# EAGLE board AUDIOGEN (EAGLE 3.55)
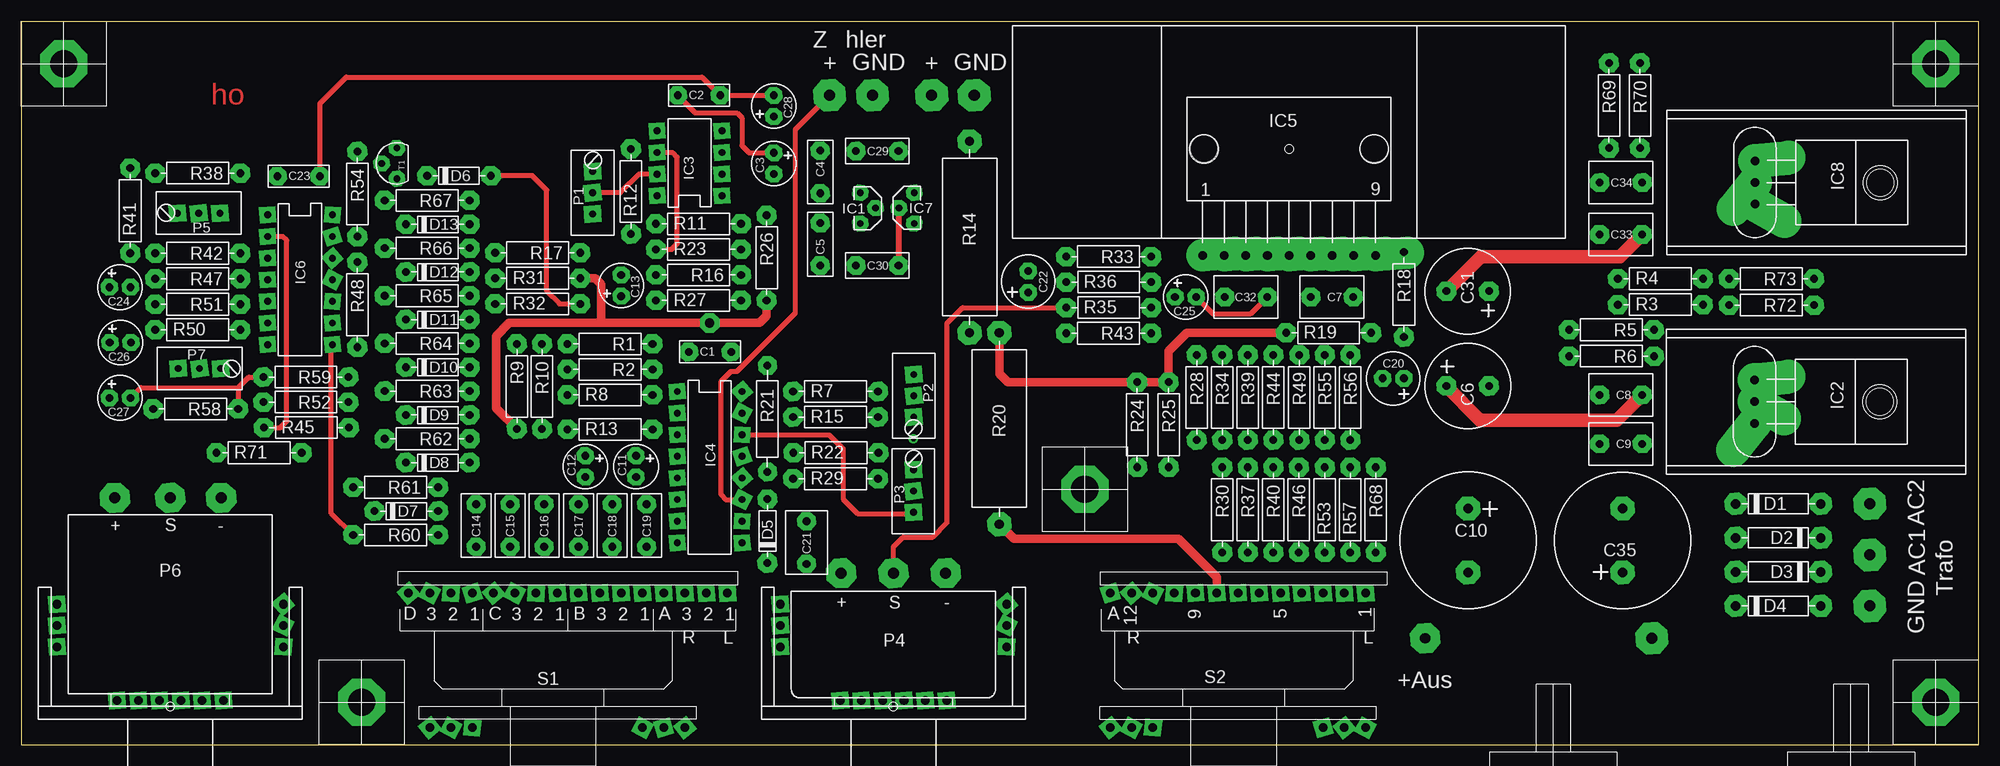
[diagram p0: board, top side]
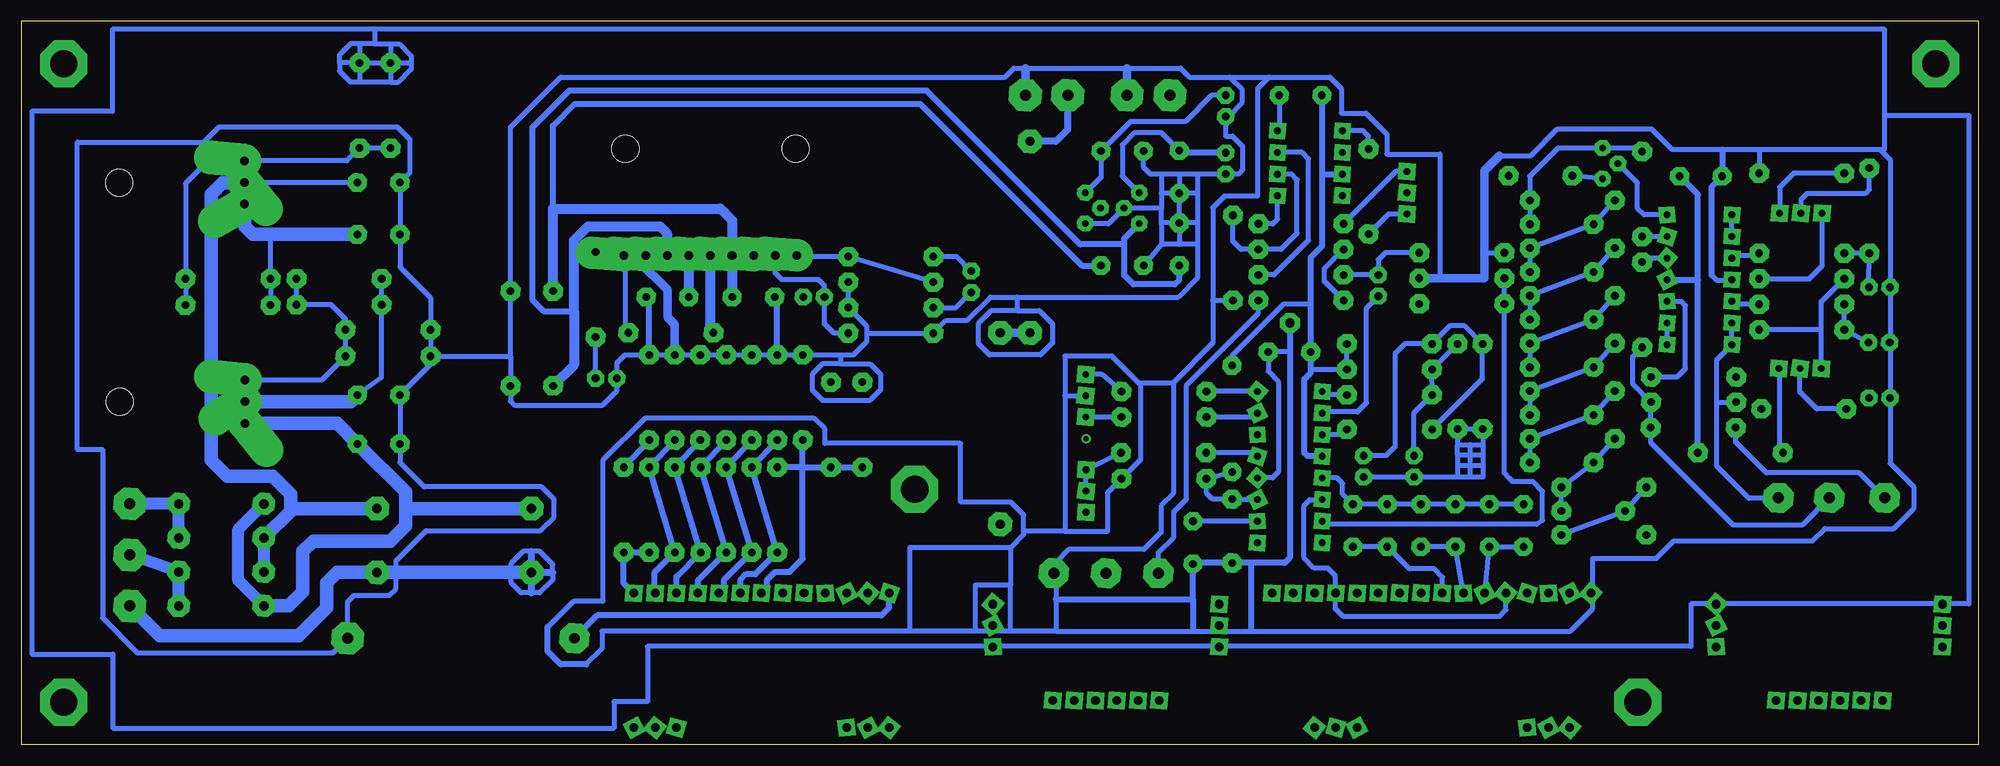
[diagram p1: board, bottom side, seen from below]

Size 230 x 85 mm. Coordinates in mm from the lower left corner, seen from the top.
Outline: 0,85 0,0 230,0 230,85 0,85
Copper layers used: Top, Bottom

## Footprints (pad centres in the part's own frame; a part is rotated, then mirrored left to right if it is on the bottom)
AD-3,8 = drill 1.3 pad 3.8 octagon:  0,0
5-2,8 = drill 0.9 pad 2.2 octagon:  0,0;  5,0
5-R2,5 = drill 0.9 pad 2 octagon:  0,0;  0,2.5
5-3,0 = drill 0.9 pad 2.2 octagon:  0,0;  5,0
0-R5 = drill 0.9 pad 2.3 octagon:  0,0;  0,5
-5,0 = drill 0.9 pad 2.2 octagon:  0,0;  5,0
6-R7,5 = drill 1.1 pad 2.8 octagon:  0,0;  0,7.5
5-3,5 = drill 0.9 pad 2.2 octagon:  0,0;  5,0
6-R2,5 = drill 0.9 pad 2 octagon:  0,0;  0,2.5
5-5,0 = drill 0.9 pad 2.2 octagon:  0,0;  5,0
10-2 = drill 1.1 pad 2.6 octagon:  0,0;  10,0
7,5 = drill 0.9 pad 2.3 octagon:  0,0;  7.5,0
L00 = drill 0.8 pad 1.9 octagon:  -1.8,1.8;  0,3.6;  0,0
317-LK = drill 1 pad 4 offset:  0,-14.75;  2.54,-14.75;  -2.54,-14.75 | hole 3.2: 0,0
L08 = drill 0.8 pad 1.9 square:  0,0;  2.54,0;  5.08,0;  7.62,0;  7.62,7.62;  5.08,7.62;  2.54,7.62;  0,7.62
L16 = drill 0.8 pad 1.9 square:  0,0;  2.54,0;  5.08,0;  7.62,0;  10.16,0;  12.7,0;  15.24,0;  17.78,0;  17.78,7.62;  15.24,7.62;  12.7,7.62;  10.16,7.62;  7.62,7.62;  5.08,7.62;  2.54,7.62;  0,7.62
A1514 = drill 1 pad 3.8 offset:  0,-12.5;  -10.16,-12.5;  -7.62,-12.5;  -5.08,-12.5;  -2.54,-12.5;  2.54,-12.5;  5.08,-12.5;  7.62,-12.5;  10.16,-12.5 | hole 3.2: -10,0; 10,0
L14 = drill 0.8 pad 1.9 square:  0,0;  2.54,0;  5.08,0;  7.62,0;  10.16,0;  12.7,0;  15.24,0;  15.24,7.62;  12.7,7.62;  10.16,7.62;  7.62,7.62;  5.08,7.62;  2.54,7.62;  0,7.62
337-LK = drill 1 pad 4 offset:  0,-14.75;  2.54,-14.75;  -2.54,-14.75 | hole 3.2: 0,0
AD-3,5 = drill 1.2 pad 3.5 octagon:  0,0
IMM-S1 = drill 0.8 pad 2 square:  0,0;  2.5,0;  -2.5,0
NTUR-1 = drill 1 pad 2 square:  -13.3,7;  -13.3,9.5;  -13.3,12;  13.3,12;  13.3,9.5;  13.3,7;  6.25,0.7;  3.75,0.7;  1.25,0.7;  -1.25,0.7;  -3.75,0.7;  -6.25,0.7 | drill 1.3 pad 3.5 octagon:  0,15.65;  6.15,15.65;  -6.15,15.65
NTUR-2 = drill 1 pad 2 square:  -13.3,7;  -13.3,9.5;  -13.3,12;  13.3,12;  13.3,9.5;  13.3,7;  6.25,0.7;  3.75,0.7;  1.25,0.7;  -1.25,0.7;  -3.75,0.7;  -6.25,0.7 | drill 1.3 pad 3.5 octagon:  0,24.5;  -6.5,24.5;  6,24.5
10 = drill 0.9 pad 2.3 octagon:  0,0;  10,0
D-6X18 = drill 1.1 pad 2.8 octagon:  0,0;  22.5,0
12,5 = drill 0.9 pad 2.2 octagon:  0,0;  12.5,0
4X03 = drill 1 pad 2 square:  -14.5,13.3;  -12,13.3;  -9.5,13.3;  -7,13.3;  -4.5,13.3;  -2,13.3;  0.5,13.3;  3,13.3;  5.5,13.3;  8,13.3;  10.5,13.3;  13,13.3;  15.5,13.3;  18,13.3;  -14.5,-2.5;  -12,-2.5;  -9.5,-2.5;  13,-2.5;  15.5,-2.5;  10.5,-2.5;  20.5,13.3;  -17,13.3
1X12 = drill 1 pad 2 square:  -14.5,13.3;  -12,13.3;  -9.5,13.3;  -7,13.3;  -4.5,13.3;  -2,13.3;  0.5,13.3;  3,13.3;  5.5,13.3;  8,13.3;  10.5,13.3;  13,13.3;  15.5,13.3;  -14.5,-2.5;  -12,-2.5;  -9.5,-2.5;  13,-2.5;  15.5,-2.5;  10.5,-2.5
-TO92 = drill 0.8 pad 1.9 octagon:  1.8,1.8;  3.6,0;  0,0

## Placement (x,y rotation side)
-VAC  GND  [AD-3,8]  217.25,16.3 0 top
BEF1  [F10]  5,80 0 top
BEF2  [F10]  225,80 0 top
BEF3  [F10]  40,5 0 top
BEF4  [F10]  125,30 0 top
BEF5  [F10]  225,5 0 top
C1  100n  [5-2,8]  78.45,46.15 0 top
C2  100n  [5-2,8]  77.15,76.3 0 top
C3  47u  [5-R2,5]  88.45,67.05 0 top
C4  220n  [5-3,0]  93.9,69.8 270 top
C5  330n  [5-3,0]  93.9,56.3 90 top
C6  470u  [0-R5]  172.5,42.15 90 top
C7  1u  [-5,0]  156.55,52.6 180 top
C8  330n  [-5,0]  190.5,41.1 180 top
C9  330n  [-5,0]  190.5,35.35 180 top
C10  2200u  [6-R7,5]  170.05,20.25 0 top
C11  10u  [5-R2,5]  72.25,31.45 0 top
C12  10u  [5-R2,5]  66.3,31.45 0 top
C13  22u  [5-R2,5]  70.5,55.2 180 top
C14  Abgl  [5-3,5]  53.45,28.25 270 top
C15  9n5  [5-3,5]  57.45,28.25 270 top
C16  Abgl  [5-3,5]  61.45,28.25 270 top
C17  47n5  [5-3,5]  65.5,28.25 270 top
C18  Abgl  [5-3,5]  69.45,28.25 270 top
C19  190n  [5-3,5]  73.5,28.25 270 top
C20  220u  [6-R2,5]  160,43.05 270 top
C21  1u  [5-5,0]  92.3,26.25 270 top
C22  22u  [6-R2,5]  118.35,55.65 180 top
C23  100n  [5-2,8]  30.1,66.8 0 top
C24  22u  [5-R2,5]  12.85,53.75 90 top
C25  4u7  [5-R2,5]  138.1,52.6 90 top
C26  22u  [5-R2,5]  12.9,47.25 90 top
C27  22u  [5-R2,5]  12.85,40.75 90 top
C28  47u  [5-R2,5]  88.45,76.3 180 top
C29  220n  [5-3,0]  98.1,69.75 0 top
C30  330n  [5-3,0]  98.1,56.3 0 top
C31  470u  [0-R5]  167.5,53.3 270 top
C32  1u  [-5,0]  146.45,52.6 180 top
C33  330n  [-5,0]  185.5,59.95 0 top
C34  330n  [-5,0]  185.5,66.05 0 top
C35  2200u  [6-R7,5]  188.2,27.75 180 top
D1  1N4003  [10-2]  201.5,28.3 0 top
D2  1N4003  [10-2]  211.5,24.3 180 top
D3  1N4003  [10-2]  211.5,20.3 180 top
D4  1N4003  [10-2]  201.5,16.3 0 top
D5  1N4148  [7,5]  87.7,21.35 90 top
D6  1N4148  [7,5]  47.7,66.85 0 top
D7  1N4148  [7,5]  41.5,27.45 0 top
D8  1N4148  [7,5]  45.2,33.15 0 top
D9  1N4148  [7,5]  45.2,38.75 0 top
D10  1N4148  [7,5]  45.2,44.35 0 top
D11  1N4148  [7,5]  45.2,49.95 0 top
D12  1N4148  [7,5]  45.2,55.55 0 top
D13  1N4148  [7,5]  45.2,61.15 0 top
IC1  78L15  [L00]  98.6,64.85 180 top
IC2  LM317  [317-LK]  218.45,40.3 270 top
IC3  TL071  [L08]  82.35,64.5 90 top
IC4  XR2206  [L16]  77.1,41.5 270 top
IC5  TDA1514  [A1514]  149,70 0 top
IC6  TL074  [L14]  28.95,62.25 270 top
IC7  79L15  [L00]  104.95,61.25 0 top
IC8  LM337  [337-LK]  218.5,66.05 270 top
KK  [48-25]  149,72 0 top
OUT  Ausgang  [AD-3,5]  165,12.5 0 top
OUT-GND  [AD-3,8]  191.65,12.5 0 top
P1  10k  [IMM-S1]  67.15,64.85 90 top
P2  20k  [IMM-S1]  104.9,41 270 top
P3  500  [IMM-S1]  104.85,29.8 90 top
P4  4k7 lin  [NTUR-1]  102.5,4.5 0 top
P5  500  [IMM-S1]  20.85,62.45 180 top
P6  10k lin  [NTUR-2]  17.5,4.5 0 top
P7  200  [IMM-S1]  20.95,44.2 0 top
POLKL+  [LKL-1]  not placed on the board
POLKL-  [LKL-1]  not placed on the board
R1  47k  [10]  74.2,47.1 180 top
R2  82k  [10]  74.2,44.1 180 top
R3  120  [10]  187.65,51.7 0 top
R4  Abgl  [10]  187.65,54.75 0 top
R5  3k3  [10]  191.9,48.75 180 top
R6  3k3  [10]  191.9,45.65 180 top
R7  10k  [10]  90.7,41.5 0 top
R8  33k  [10]  64.2,41.1 0 top
R9  47k  [10]  58.25,47.1 270 top
R10  33k  [10]  61.2,47.1 270 top
R11  4.7k  [10]  74.6,61.2 0 top
R12  4.7k  [10]  71.65,60 90 top
R13  33k  [10]  64.2,37.05 0 top
R14  47  [D-6X18]  111.45,70.9 270 top
R15  10k  [10]  90.7,38.5 0 top
R16  100  [10]  84.6,55.2 180 top
R17  33k  [10]  65.7,57.8 180 top
R18  2k2  [10]  162.5,57.9 270 top
R19  20k  [10]  148.65,48.4 0 top
R20  47  [D-6X18]  114.95,48.4 270 top
R21  4k7  [12,5]  87.7,44.55 270 top
R22  120  [10]  90.75,34.3 0 top
R23  22k  [10]  74.6,58.2 0 top
R24  300  [10]  131.15,42.6 270 top
R25  300  [10]  134.85,42.6 270 top
R26  10k  [10]  87.6,62.2 270 top
R27  47  [10]  74.6,52.2 0 top
R28  101R5  [10]  138.15,45.8 270 top
R29  300  [10]  90.7,31.25 0 top
R30  150  [10]  141.15,32.6 270 top
R31  4M7  [10]  55.7,54.8 0 top
R32  2k4  [10]  55.7,51.8 0 top
R33  39k  [10]  132.8,57.35 180 top
R34  101R5  [10]  141.15,45.8 270 top
R35  1M  [10]  122.8,51.35 0 top
R36  20k  [10]  122.8,54.35 0 top
R37  150  [10]  144.15,32.6 270 top
R38  3k3  [10]  25.75,67.15 180 top
R39  101R5  [10]  144.15,45.8 270 top
R40  150  [10]  147.15,32.6 270 top
R41  10k  [10]  12.8,57.75 90 top
R42  100  [10]  25.75,57.75 180 top
R43  470k  [10]  132.8,48.35 180 top
R44  101R5  [10]  147.15,45.8 270 top
R45  1M  [10]  28.5,37.25 0 top
R46  150  [10]  150.15,32.6 270 top
R47  2k2  [10]  25.75,54.75 180 top
R48  100  [10]  39.5,56.7 270 top
R49  101R5  [10]  150.2,45.8 270 top
R50  10k  [10]  15.75,48.75 0 top
R51  100  [10]  25.75,51.75 180 top
R52  1M  [10]  38.45,40.25 180 top
R53  150  [10]  153.2,22.6 90 top
R54  680  [10]  39.5,69.7 270 top
R55  101R5  [10]  153.2,45.8 270 top
R56  1  [10]  156.2,45.8 270 top
R57  150  [10]  156.2,22.6 90 top
R58  10k  [10]  25.5,39.45 180 top
R59  100  [10]  38.45,43.2 180 top
R60  270  [10]  49,24.65 180 top
R61  1k  [10]  49,30.25 180 top
R62  2k  [10]  52.7,35.95 180 top
R63  3k9  [10]  52.7,41.55 180 top
R64  8k2  [10]  52.7,47.15 180 top
R65  16k  [10]  52.7,52.75 180 top
R66  33k  [10]  52.7,58.35 180 top
R67  68k  [10]  52.7,63.95 180 top
R68  68  [10]  159.2,32.6 270 top
R69  3k3  [10]  186.6,80.1 270 top
R70  3k3  [10]  190.25,80.1 270 top
R71  1k3  [10]  22.95,34.3 0 top
R72  120  [10]  210.7,51.65 180 top
R73  Abgl  [10]  210.7,54.75 180 top
S1  LRN 4x3 k  [4X03]  62.5,4.5 0 top
S2  LRN 1x12 u  [1X12]  142.5,4.5 0 top
T1  BC550C  [-TO92]  44.15,66.5 90 top
V-GND  [AD-3,8]  112,76.3 0 top
V-OUT  [AD-3,8]  107,76.3 0 top
VAC1  AC2  [AD-3,8]  217.25,28.3 0 top
VAC2  AC1  [AD-3,8]  217.25,22.3 0 top
Z-GND  [AD-3,8]  100.05,76.3 0 top
Z-OUT  Zum Zhler  [AD-3,8]  95,76.3 90 top

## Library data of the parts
-VAC OUT OUT-GND V-GND V-OUT VAC1 VAC2 Z-GND Z-OUT = PADS
BEF1-BEF5 = MECHANIK
C1-C35 D1-D13 IC3 IC4 IC6 R1-R13 R15-R19 R21-R73 T1 = EAGLE
IC1 IC2 IC7 IC8 = U-STABI
IC5 KK R14 R20 = Audiogen
P1-P7 = POTIS
POLKL+ POLKL- = BUCHSEN
S1 S2 = LRN-SCH

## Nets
+15V: C1. C2. C3. C4. IC1. IC3. IC4. P1. R1. R2. R21.
+19V: C5. C6. C7. C8. IC1. IC2. IC5. R3. R4.
+UB: C9. C10. D1. D4. IC2.
-15V: C2. C23. C28. C29. IC3. IC6. IC7. R71.
-19V: C25. C30. C31. C32. C33. IC5. IC7. IC8. R72. R73.
-UB: C34. C35. D2. D3. IC8.
AUS: IC5. R14. R19. R20. R24. R25.
GND: -VAC. C1. C3. C4. C5. C6. C7. C8. C9. C10. C11. C12. C20. C21. C23. C24. C26. C27. C28. C29. C30. C31. C32. C33. C34. C35. D5. IC1. IC4. IC5. IC6. IC7. OUT-GND. P2. P4. R5. R6. R9. R10. R17. R26. R28. R29. R31. R34. R35. R36. R38. R39. R43. R44. R49. R55. R56. R69. R70. V-GND. Z-GND.
N$1: IC4. R7.
N$2: IC4. R15.
N$3: P2. R7.
N$4: P2. R15.
N$5: IC4. P3.
N$6: IC4. R22.
N$7: P3. R22.
N$8: C11. R1. R9. R13.
N$9: C16. C17. S1.
N$10: IC4. S1.
N$11: C21. IC4.
N$12: IC4. R8.
N$13: IC4. R13.
N$14: P7. R71.
N$15: C12. R2. R8. R10.
N$16: C13. IC4.
N$17: C13. R16. R17.
N$18: C14. C15. C16. C17. C18. C19. IC4.
N$19: C14. C15. S1.
N$20: IC6. P6. R52.
N$21: C18. C19. S1.
N$22: IC4. R31. R32.
N$23: IC6. P6. R45.
N$24: P6. R45. R48. R52.
N$25: P5. R41.
N$26: P7. R58.
N$27: C24. R41. R42.
N$28: IC6. R42.
N$29: P1. R11.
N$30: C27. R58. R59.
N$31: IC6. R59.
N$32: IC6. R48.
N$33: IC6. R60.
N$34: IC6. R51.
N$35: IC3. R16.
N$36: IC3. R23. R26.
N$37: P5. R38.
N$38: P7. R47. R50.
N$39: D13. R54. R67. T1.
N$40: IC6. R54.
N$41: P5. R47.
N$42: P1. R12.
N$43: IC6. T1.
N$44: D7. R60. R61.
N$45: D7. D8. R61. R62.
N$46: D8. D9. R62. R63.
N$47: D9. D10. R63. R64.
N$48: D10. D11. R64. R65.
N$49: D11. D12. R65. R66.
N$50: D12. D13. R66. R67.
N$51: IC3. R23. R27.
N$52: D6. T1.
N$53: D6. R32.
N$54: P4. R27.
N$55: OUT. S2.
N$56: C26. R50. R51.
N$57: IC3. R12.
N$58: R14. V-OUT.
N$59: IC5. R18. R19.
N$61: D1. D2. VAC1.
N$62: C25. IC5. R43.
N$63: D3. D4. VAC2.
N$64: C20. R18.
N$66: IC5. R33. R36.
N$67: C22. P4. R35.
N$68: C22. R33.
N$73: R46. R49. R53. S2.
N$74: R53. R55. R57. S2.
N$76: R57. R68. S2.
N$80: IC8. R69. R70. R72. R73.
N$82: IC2. R3. R4. R5. R6.
N$86: IC3. R11.
N$94: R40. R44. R46. S2.
N$95: R30. R34. R37. S2.
N$96: R37. R39. R40. S2.
N$97: R20. S2.
N$99: R56. R68.
S2: R24. R25. R28. R30. S2.
TTL-OUT: D5. IC4. R21. R29. Z-OUT.

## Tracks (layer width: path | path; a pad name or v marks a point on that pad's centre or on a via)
+15V
  Top 0.6: 74.73,67.04 74.7,67.05 72.6,67.05 70.4,64.85 67.15,64.85 | C3. 85.55,69.55 84.7,70.4 84.7,73.65 84.1,74.25 79.2,74.25 77.15,76.3
  Bottom 0.6: 77.1,76.3 77.15,76.3 | 74.2,47.1 74.2,44.1 78.45,44.1 | IC1. 98.65,64.85 100.6,66.8 100.6,70.5 99.2,71.9 96,71.9 93.9,69.8 | 87.7,44.55 87.7,45.7 81.65,51.75 78.45,51.75
  Bottom 0.7: 77.1,67.05 77.1,76.3 | 77.1,67.05 77.1,58.6 78.45,57.25 78.45,51.75 78.45,46.15 78.45,44.1 78.45,43.7 79.2,42.95 79.2,34.3 78.8,33.9 77.05,33.9 | 77.1,33.88 77.05,33.9 | 77.05,33.9 77,33.85 | 74.73,67.04 74.75,67.05 77.1,67.05 | C3. 93.65,69.55 93.9,69.8
+19V
  Top 1.6: 190.5,41.1 187.55,38.15 171.45,38.15 167.45,42.15 C6.
  Bottom 0.6: 154.1,57.5 154.08,57.5 | 190.5,41.1 187.65,43.15 187.65,51.7 187.65,54.75
  Bottom 0.7: 98.6,61.25 100.35,59.5 100.35,58.8 | 93.9,56.3 93.9,54.65 94.45,54.1 99.3,54.1 100.35,55.15 100.35,58.8 | 100.35,58.8 105.55,58.8 123.6,76.85 165.6,76.85 169.95,72.5 169.95,52.3 168.6,50.95 165.05,50.95
  Bottom 1.2: 154.08,57.5 151.54,57.5 151.55,57.5 C7. | 154.1,57.5 154.1,60.1 154.9,60.9 163.4,60.9 165.05,59.25 165.05,50.95 165.05,44.6 C6.
  Bottom 1.6: 190.5,41.1 191.3,40.3 203.7,40.3
+UB
  Bottom 1.4: 201.5,28.3 204.5,25.3 204.5,19.3 201.5,16.3
  Bottom 1.6: 203.7,37.76 199.1,37.75 192.9,37.75 190.5,35.35 184.85,29.7 184.85,27.75 | C10. 184.85,27.75 | 184.85,27.75 184.85,25.7 186.65,23.9 195.7,23.9 196.9,22.7 196.9,17.95 198.55,16.3 201.5,16.3
-15V
  Top 0.6: C23. 35.1,75.35 38.2,78.45 80,78.45 C2. 88.45,76.3
  Bottom 0.6: 104.95,64.85 104.9,64.85 103.1,66.65 C29. 99.65,73.2 93.2,73.2 90.1,76.3 88.45,76.3 | 82.35,72.12 82.15,72.3 C2.
  Bottom 0.7: 36.57,54.63 36.55,54.6 32.95,54.6 | 32.95,54.6 32.95,64.65 C23. | R71. 32.95,54.6
-19V
  Top 0.6: 146.45,52.6 144.45,50.6 140.1,50.6 138.1,52.6
  Top 0.7: 103.15,63.05 103.15,56.3 C30.
  Top 1.6: C33. 187.9,57.35 171.55,57.35 167.5,53.3
  Bottom 0.6: 200.7,59.95 R73. R72.
  Bottom 0.7: C30. 105.35,56.3 124.35,75.3 164.95,75.3 167.5,72.75 167.5,63
  Bottom 1: 146.46,52.6 146.45,52.6
  Bottom 1.2: 146.46,52.6 146.46,57.5 146.46,61.6 147.3,62.45 147.85,63 167.5,63 167.5,53.3
  Bottom 1.6: 203.75,63.51 203.75,60.9 202.8,59.95 200.7,59.95 C33.
-UB
  Bottom 0.6: C34. 203.75,66.05
  Bottom 1.4: D2. D3.
  Bottom 1.6: 203.75,66.05 206.3,66.05 207.7,64.65 207.7,35.8 207.7,33.4 205.8,31.55 200.45,31.55 198.35,29.45 198.35,27.75 | 198.35,27.75 188.2,27.75 | D2. 198.35,27.45 198.35,27.75
AUS
  Top 1: 114.95,48.4 114.95,43.6 115.95,42.6 131.15,42.6 134.85,42.6 134.85,46.25 137,48.4 148.65,48.4
  Bottom 1: 114.95,48.4 R14.
  Bottom 1.2: 148.65,48.4 149,48.75 149,57.5
GND  (via drill 1.1 pad 2.3)
  Top 0.3: 81,49.55 v80.9,49.55
  Top 1: R31. 67.45,54.8 68.15,54.1 68.15,49.6 | R9. 55.8,39.55 55.8,48 57.35,49.55 81,49.55 86.75,49.55 87.6,50.4 R26.
  Bottom 0.3: 96,61.3 96,61.25
  Bottom 0.6: 10.35,47.25 C26. | 10.35,47.25 C24. 10.35,68.75 11.55,69.95 | 10.35,47.25 C27. 10.35,33.05 7.6,30.3 7.6,27.75 9.95,25.4 18.05,25.4 19.5,23.95 35.8,23.95 37.85,21.9 45.3,21.9 45.3,16 47.95,13.35 108.4,13.35 | 61.2,35.25 R10. 61.15,37.05 58.3,37.05 R9. 58.2,37.1 58.2,34 | 61.2,34 61.2,35.25 | 61.2,34 61.2,32.8 | 61.2,32.8 61.2,31.45 | 61.2,31.45 66.3,31.45 72.25,31.45 | 59.7,31.45 58.2,31.45 58.2,32.8 | 59.7,31.45 61.2,31.45 | 58.2,34 58.2,32.8 | 58.2,32.8 61.2,32.8 | 58.2,34 61.2,34 | 61.2,35.25 59.7,35.25 | 59.7,35.25 58.2,35.25 | 59.7,31.45 59.7,35.25 | C1. 83.45,46.1 | C1. 83.45,43.85 82.25,42.65 82.25,32.05 82.95,31.35 84.7,31.35 84.72,31.34 | 80.9,46.15 C1. | C28. 88.45,73.25 | 89.95,52.2 R26. | 91.75,67.05 93.9,67.05 | 91.75,67.05 88.45,67.05 86.95,67.05 86.45,67.55 86.45,70.3 87.65,71.5 88.45,71.5 C28. | 91.75,67.05 91.75,64.8 | 91.75,64.8 91.75,61.3 | 93.9,67.05 C4. | C5. 93.9,64.75 | 91.75,64.8 C4. | 96,63.05 100.4,63.05 102.25,61.2 104.95,61.2 IC7. | 96,64.75 96,64.8 C4. | 96,64.75 96,63.05 | 96,63.05 96,61.3 C5. | 91.75,61.3 C5. | 91.75,58.8 93.9,58.8 | 93.9,58.8 95.65,58.8 | 91.75,61.3 91.75,58.8 | 91.75,58.8 91.75,54.85 94,52.6 113,52.6 | C5. 93.9,58.8 | 96,61.25 96,58.8 98.1,56.3 | 96,67.05 96,64.75 | 93.9,67.05 96,67.05 | 96,67.05 97.3,67.05 98.1,67.85 98.1,69.75 | 28.95,54.63 28.9,54.6 30.75,54.6 31.35,55.2 | 94.6,42.45 98.45,42.45 98.45,42.3 | 56.3,69.2 52.6,69.2 49.45,72.35 38.4,72.35 36,69.95 30.1,69.95 25.75,69.95 | 58.05,57.8 R17. | 25.75,69.95 25.75,67.15 | 63.25,54.8 63.25,69.4 69.5,69.4 69.5,71.75 71.95,74.2 74.85,74.2 74.85,77.1 76.2,78.45 83.35,78.45 | 89.95,52.2 89.95,47.2 94.6,42.55 94.6,42.45
  Bottom 0.6: 89.95,52.2 89.95,63.1 88.6,64.45 84.7,64.45 84.7,77.1 83.35,78.45 | 94.6,42.45 94.6,29.5 96.05,28.05 96.05,24.95 98.05,22.95 106.9,22.95 108.4,21.45 108.4,20.15 | 107.35,41 107.35,45.65 101.8,45.65 98.45,42.3 | 107.35,25.05 102.35,25.05 102.35,29.6 R29. 98.45,33.5 98.45,42.3 | 107.35,41 107.35,25.05 | 107.35,41 104.9,41 | 87.95,78.45 92.7,78.45 93.75,79.5 100.05,79.5 112,79.5 113.35,79.5 114.4,78.45 166.6,78.45 172.5,72.55 C31. 172.5,45.65 | R36. R35. 130.6,49.15 130.6,48.35 | 11,73.95 1.1,73.95 1.1,16.55 33.75,16.55 33.75,11.55 156.4,11.55 156.4,5.05 160.35,5.05 160.35,1.95 219.25,1.95 219.25,10.65 228.75,10.65 228.75,74.4 219.3,74.4 219.3,84.05 188.45,84.05 | 11,73.95 11,84.05 188.45,84.05 | C28. 88.15,73.8 86.55,75.4 86.55,77.05 87.95,78.45 | 87.95,78.45 83.35,78.45 | 133.7,44.75 130.25,44.75 129,43.5 129,41.7 130.25,40.45 135.8,40.45 137.05,41.7 137.05,43.5 135.8,44.75 133.7,44.75 | 113,51 116,51 117.55,49.45 117.55,47.15 116.2,45.8 110.2,45.8 108.8,47.2 108.8,49.45 110.35,51 113,51 | 168.15,13.8 165.1,16.85 161.65,16.85 161.65,33.4 156.7,38.35 136.8,38.35 135.55,37.1 135.55,35.4 119.6,35.4 119.6,28.5 113.7,28.5 112.2,27 112.2,25.05 | 172.5,45.65 172.5,42.15 172.5,40.35 172.05,39.9 161.7,39.9 160,41.6 160,43.05 160,44.85 159.05,45.8 156.2,45.8 153.2,45.8 150.2,45.8 147.15,45.8 144.15,45.8 141.15,45.8 138.15,45.8 133.7,45.8 | 130.6,48.35 R43. 121.3,49.85 118.85,49.85 116.1,52.6 113,52.6 | 130.6,48.35 130.6,47.4 132.2,45.8 133.7,45.8 | 113,52.6 113,51 | 108.4,20.15 108.4,17.1 108.4,13.35 | 108.4,20.15 108.65,20.15 | 112.2,25.05 112.2,24.7 113.75,23.15
  Bottom 0.6: 107.35,25.05 112.2,25.05 | 113.75,13.35 117.9,13.35 | 117.9,13.35 161.75,13.35 161.75,11.3 163.6,9.45 | 185.5,59.95 185.5,59.9 | 185.5,59.95 185.5,66.05 184.35,67.2 184.35,71.15 185.8,72.6 206.75,72.6 208.55,70.8 223.4,70.8 223.4,34.7 220.45,34.7 220.45,14.9 216.35,10.8 193.35,10.8 OUT-GND. 191.65,16.8 190.9,17.55 186.75,17.55 185.95,18.35 185.95,20.25 185.95,21.6 182.4,25.15 169,25.15 167.4,26.75 167.4,28.85 168.85,30.3 182.65,30.3 185.5,33.15 C9. C8. 181.9,44.7 R6. | 185.5,59.95 185.5,56.1 181.9,52.5 R5. | R5. 181.9,48.65 | 184.15,80.1 184.15,80.9 185.6,82.35 186.6,82.35 | 184.15,80.1 184.15,79.35 185.65,77.85 186.6,77.85 | 188.45,82.35 186.6,82.35 | 188.45,82.35 190.25,82.35 | 190.25,82.35 191.3,82.35 192.6,81.05 192.6,80.1 | 192.6,80.1 192.6,79.15 191.3,77.85 190.25,77.85 | 186.6,77.85 190.25,77.85 | 186.6,80.1 186.6,77.85 | 186.6,82.35 186.6,80.1 | 190.25,80.1 190.25,77.85 | 190.25,82.35 190.25,80.1 | 190.25,80.1 186.65,80.1 | 186.6,80.1 186.65,80.1 | 188.45,84.05 188.45,82.35 | R5. R6. | 190.25,80.1 192.6,80.1 | 186.65,80.1 184.15,80.1 | 25.75,69.95 11.55,69.95 | 133.7,45.8 133.7,44.75 | 108.4,13.35 113.75,13.35 | 113.75,23.15 113.75,18.75 | 113.75,13.35 113.75,18.75 | R6. 172.5,45.65 | 113.75,23.15 125.6,23.15 125.6,13.35 | 113.75,18.75 117.9,18.75 117.9,13.35 | 11.55,69.95 11,69.95 11,73.95 | 167.55,20.25 167.55,19.35 169.05,17.85 171.25,17.85 172.4,19 172.4,21.3 171,22.7 170.05,22.7 169.05,22.7 167.55,21.2 167.55,20.25
  Bottom 0.7: v80.9,49.55 80.9,46.15 80.9,21.95 81.5,21.35 85.45,21.35 | 31.35,55.2 31.35,65.55 30.1,66.8 30.1,69.95 | 85.45,21.35 87.7,21.35 91.55,21.35 C21. 92.3,17.1 | C32. 141.15,52.3 141.15,45.8 | 156.55,52.6 156.2,52.25 156.2,45.8 | 85.45,21.35 85.45,13.4 | 92.3,17.1 92.3,13.4 | 168.15,13.8 168.15,11 166.6,9.45 163.6,9.45 | 108.4,17.1 92.3,17.1
  Bottom 0.8: 170.05,20.25 167.55,20.25 | 170.05,22.7 170.05,17.85
  Bottom 1: R31. 63.25,54.8 58.05,54.8 58.05,57.8 58.05,67.45 56.3,69.2 | 100.05,79.5 Z-GND. | 112,79.5 V-GND. | 156.62,57.5 156.62,56 154.95,54.35 154.05,53.45 154.05,50.25 153.2,49.4 153.2,45.8
  Bottom 1.6: 170.05,20.25 185.95,20.25 C35. 192.9,20.25 194.1,19.05 194.1,16.1 197.4,12.8 213.75,12.8 -VAC.
N$1
  Bottom 0.6: 84.7,41.5 IC4. 90.7,41.5
N$2
  Bottom 0.6: 84.72,38.96 85.2,38.5 90.7,38.5
N$3
  Bottom 0.6: R7. 103,43.5 P2.
N$4
  Bottom 0.6: R15. 104.9,38.5
N$5
  Top 0.6: 84.72,36.42 84.8,36.4 94.95,36.4 96.6,34.75 96.6,28.85 98.3,27.15 104.7,27.15 P3.
N$6
  Bottom 0.6: 84.72,33.88 85.15,34.3 90.75,34.3
N$7
  Bottom 0.6: R22. 104.85,32.3 104.85,29.8
N$8
  Bottom 0.3: 72.2,33.95 C11.
  Bottom 0.6: 72.2,33.95 69.6,33.95 68.55,35 68.55,45.95 67.4,47.1 R1. 62.1,49.2 60.35,49.2 58.25,47.1 58.25,43 64.2,37.05
N$9
  Bottom 0.6: C17. C16. 60.5,17.8
N$10
  Bottom 0.6: 77.1,28.8 78.55,28.8 79.25,28.1 79.25,21.95 78.05,20.75 76.45,20.75 75.55,19.85 75.55,16 74.6,15.05 56.3,15.05 55.5,15.85 55.5,17.8
N$11
  Bottom 0.6: 84.72,26.26 84.75,26.25 92.3,26.25
N$12
  Bottom 0.6: 77.1,41.5 77.05,41.5 77.05,41.1 R8.
N$13
  Bottom 0.6: R13. 74.15,37.05 74.8,36.4 77.1,36.42
N$14
  Bottom 0.6: 23.45,44.2 23.3,44.05 23.3,34.65 22.95,34.3
N$15
  Bottom 0.6: 61.2,47.1 64.15,44.05 R2. 64.15,41.05 64.2,41.1 66.3,39 C12.
N$16
  Bottom 0.6: C13. 71.9,51.3 71.9,40.15 72.95,39.1 77.1,39.1 77.1,38.96 77.1,38.95
N$17
  Bottom 0.6: R16. 70.5,55.2 70.5,57 69.7,57.8 65.7,57.8
N$18
  Bottom 0.6: 57.45,28.25 57.5,28.25 | 53.45,28.25 57.45,28.25 | 57.45,28.25 61.45,28.25 65.5,28.25 69.45,28.25 73.5,28.25 74.7,29.45 74.7,30.7 75.35,31.35 77.05,31.35 77.1,31.34
N$19
  Bottom 0.6: C14. C15. 58,17.75 58,17.8
N$20
  Bottom 0.6: 30.7,40.25 30.7,45.25 28.95,47 28.95,47.01 28.9,47 28.95,47.05 28.95,49.55 | 30.7,40.25 R52. | 30.7,40.25 30.7,32.7 26.95,28.95 23.45,28.95 P6.
N$21
  Bottom 0.6: C19. C18. 66.85,20.65 63.9,20.65 62.95,19.7 62.95,17.8 63,17.8
N$22
  Bottom 0.6: 77.1,26.26 77.1,25.9 51.9,25.9 51.2,26.35 51.2,29.8 52.3,30.9 54.7,30.9 55.1,31.3 55.7,31.95 55.7,51.8 55.7,54.8
N$23
  Top 0.6: 28.95,59.71 30.75,59.7 31.2,59.25 31.2,38 30.45,37.25 28.5,37.25 28.45,37.25
  Bottom 0.6: 28.95,62.25 28.95,59.71 28.95,59.7 | 28.5,37.25 28.5,35.55 24.9,31.95 14,31.95 11,28.95 11,29
N$24
  Bottom 0.6: 38.45,37.3 R45. | 38.45,37.3 38.45,40.25 40.6,42.4 40.6,45.6 R48. | 38.45,37.3 38.45,35.45 28.8,25.8 20.7,25.8 17.5,29
N$25
  Bottom 0.6: 20.85,62.45 20.85,64.05 20.15,64.75 13.3,64.75 12.8,65.25 R41.
N$26
  Bottom 0.6: 20.95,44.2 20.95,41.45 18.95,39.45 R58.
N$27
  Bottom 0.6: R42. 12.8,57.75 12.85,53.95 12.85,53.75
N$28
  Bottom 0.6: 28.95,57.17 28.65,57.45 26.05,57.45 25.75,57.75
N$29
  Bottom 0.6: 74.6,61.2 68.45,67.35 67.15,67.35
N$30
  Top 0.6: 12.85,40.75 14.05,41.95 25.5,41.95 | 25.5,41.95 26.75,43.2 R59. | 25.5,41.95 25.5,39.45
N$31
  Bottom 0.6: 38.45,43.2 35.4,43.2 34.4,44.2 34.4,51.6 34.85,52.05 36.55,52.05 36.57,52.09
N$32
  Bottom 0.6: 39.5,56.7 39.5,56.65 39,57.17 36.57,57.17
N$33
  Top 0.6: 36.57,47.01 36.45,46.9 36.45,27.15 38.95,24.65 R60.
  Bottom 0.6: 36.55,49.55 36.5,49.55 | 36.55,49.55 36.57,49.55 | 36.57,47.01 36.55,47.05 36.55,49.55
N$34
  Bottom 0.6: 25.7,51.75 25.75,51.75 28.95,51.75 28.95,52.09
N$35
  Bottom 0.6: 82.3,69.55 82.35,69.58 | 82.25,69.6 79.45,69.6 78.7,68.85 78.7,59.25 82.75,55.2 84.6,55.2
  Bottom 0.7: 82.25,69.6 82.3,69.55
N$36
  Bottom 0.3: 82.35,67 82.35,67.04
  Bottom 0.6: 82.35,67 80.65,67 80.05,66.4 80.05,60.1 81.95,58.2 R23. 86.65,58.2 87.6,59.15 87.6,62.2
N$37
  Bottom 0.6: P5. 23.35,65.5 21.7,67.15 R38. 15.65,67.15
N$38
  Bottom 0.6: 18.45,44.15 P7. 18.45,48.75 | R47. 18.45,52.05 18.45,48.75 | 18.45,48.75 R50.
N$39
  Bottom 0.6: 52.7,61.1 D13. 52.7,63.95 52.7,66.8 49.4,70.1 44.15,70.1 39.9,70.1 39.5,69.7
N$40
  Bottom 0.6: 36.57,59.71 36.7,59.7 R54.
N$41
  Bottom 0.6: 18.35,62.45 18.35,56.25 19.9,54.7 25.7,54.7 25.75,54.75
N$42
  Bottom 0.6: P1. 69.3,62.35 71.65,60
N$43
  Bottom 0.6: IC6. 39.3,62.25 40.05,63 40.05,66 42.35,68.3
N$44
  Bottom 0.6: R61. 41.5,27.45 49,24.65
N$45
  Bottom 0.6: R62. 45.2,33.15 49,30.25 D7.
N$46
  Bottom 0.6: R63. 45.2,38.75 52.7,35.95 D8.
N$47
  Bottom 0.6: R64. 45.2,44.35 52.7,41.55 D9. 52.7,38.7
N$48
  Bottom 0.6: R65. 45.2,49.95 52.7,47.15 D10.
N$49
  Bottom 0.6: R66. 45.2,55.55 52.7,52.75 D11.
N$50
  Bottom 0.6: R67. 45.2,61.15 52.7,58.35 D12. 52.7,55.5
N$51
  Top 0.6: 74.73,69.58 74.75,69.55 76.6,69.55 77.1,69.05 77.1,58.85 76.45,58.2 74.6,58.2
  Bottom 0.6: 74.6,58.2 76.85,55.95 76.85,54.45 74.6,52.2
N$52
  Bottom 0.6: T1. 47.7,66.85
N$53
  Top 0.6: D6. 60.05,66.85 61.75,65.15 61.75,53.3 63.25,51.8 R32.
N$54
  Bottom 0.6: R27. 84.6,50.7 93.05,42.25 93.05,28.85 94.55,27.35 94.55,24.4 96.35,22.6 P4. 96.35,20.1
N$55
  Bottom 0.7: 128,17.8 128,16.1 128.9,15.2 162.3,15.2 OUT.
N$56
  Bottom 0.6: 12.9,47.25 12.85,47.25 15.75,48.75 R51.
N$57
  Bottom 0.6: 74.73,72.12 72.25,72.12 71.9,71.75 71.65,71.5 R12.
N$58
  Bottom 0.8: V-OUT. 107,72.3 108.4,70.9 111.45,70.9
N$59
  Bottom 0.6: 162.5,57.9 159.55,57.9 IC5. 159,57.35 159,48.75 R19.
N$60  (via drill 0.6 pad 1.1)
  other vias: 104.85,35.95
N$61
  Bottom 1.4: VAC1. D1. 211.5,24.3
N$62
  Bottom 0.6: 141.38,57.5 141.35,57.5 | 141.38,57.5 143.92,57.5 | 141.38,57.5 141.38,55.45 141.1,55.15 140.6,54.65 136.3,54.65 135.6,53.95 C25. 135.6,49.45 134.5,48.35 132.8,48.35
N$63
  Bottom 1.4: VAC2. 211.5,20.3 D4.
N$64
  Bottom 0.6: 162.5,43 C20. R18.
N$66
  Bottom 0.6: 138.84,57.5 138.7,57.35 132.8,57.35 122.8,54.35
N$67
  Top 0.6: 122.8,51.35 110.65,51.35 108.8,49.5 108.8,26.05 107.15,24.4 103.65,24.4 102.5,23.25 102.5,20.15
  Bottom 0.6: 122.8,51.35 120.15,51.35 C22.
N$68
  Bottom 0.6: R33. 120.05,57.35 118.35,55.65
N$73
  Bottom 0.7: R49. R53. R46. 153,19.75 153,17.8
N$74
  Bottom 0.7: R55. R57. 153.2,22.6 155.55,20.25 155.55,17.8 155.5,17.8
N$76
  Bottom 0.7: 158,17.8 158.05,17.8 159.2,18.95 R68. 156.2,22.6
N$80
  Bottom 0.6: 210.7,51.65 210.7,54.75 210.7,65.95 209.7,66.95 208.05,68.59 IC8. 191.75,68.59 R70. R69.
N$82
  Bottom 0.6: R3. 197.65,51.65 | R3. R4. | R3. 193.6,51.7 191.9,50 191.9,48.75 191.9,45.65 194.7,42.84 IC2.
N$86
  Bottom 0.6: 82.35,64.5 82.35,61.75 82.9,61.2 R11.
N$94
  Bottom 0.7: 150.15,32.6 150.15,32.55 | 150.15,32.6 R44. | 150.15,32.6 147.1,22.6 R40. 150.5,19.25 150.5,17.8
N$95
  Bottom 0.7: 144.15,32.6 R34. | 144.15,32.6 144.1,32.55 | 144.15,32.6 R30. 143.75,20 144.85,20 145.5,19.35 145.5,17.8
N$96
  Bottom 0.7: R39. 147.15,32.6 144.1,22.6 R37. 147.45,19.3 147.45,18.35 148,17.8
N$97
  Top 1: R20. 116.65,24.2 136,24.2 140.5,19.7 140.5,17.8
N$99
  Bottom 0.7: 159.2,32.6 R56.
S2
  Bottom 0.7: 138.15,32.6 141.15,32.6 | R24. R25. 138.15,32.6 | 138.15,32.6 138.15,21.85 139.7,20.3 141.4,20.3 142.4,19.3 142.4,18.4 143,17.8 | 138.15,32.6 R28.
TTL-OUT
  Top 0.6: 84.72,28.8 82.8,28.8 82.25,29.35 82.25,42.7 83.4,43.85 84.1,43.85 91,50.75 91,72.3 Z-OUT.
  Bottom 0.6: 84.7,28.8 84.72,28.8 87.7,28.8 D5. 90,28.85 90.7,29.55 90.7,31.25 R21.
VIA1  (via drill 3.2 pad 5.5)
  other vias: 5,80
VIA2  (via drill 3.2 pad 5.5)
  other vias: 225,80
VIA3  (via drill 3.2 pad 5.5)
  other vias: 40,5
VIA4  (via drill 3.2 pad 5.5)
  other vias: 125,30
VIA5  (via drill 3.2 pad 5.5)
  other vias: 225,5

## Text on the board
Top: ho
tPlace: Zhler | + | GND | + | GND | AC2 | AC1 | Trafo | GND | +Aus | +Aus | -Aus | (GND)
